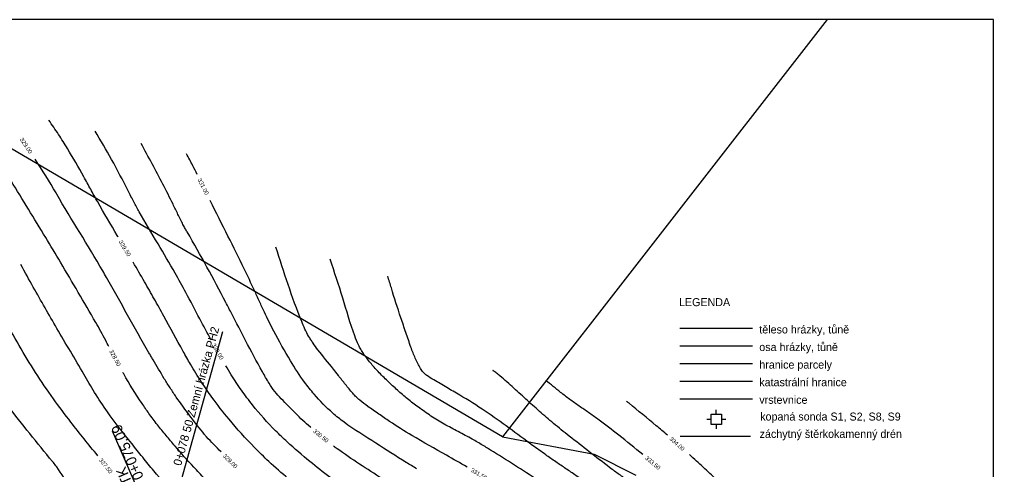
# Model space of a CAD drawing. Extents: x -564037 to -563827, y -1163561 to -1163412.
# Drawn here: x -563942.8 to -563826.5, y -1163466.2 to -1163412.5 of the extents above; entities that cross this region are included whole.
import ezdxf

# ---------------------------------------------------------------- set-up
doc = ezdxf.new("R2010")
doc.units = 0
for name, color, linetype in [('_popis staničení RT1', 7, 'Continuous'), ('_rám RT1', 7, 'Continuous'), ('Hranice parcel', 7, 'Continuous'), ('Obvod PU', 7, 'Continuous'), ('Vrstva 24', 7, 'Continuous'), ('Vrstva 25', 7, 'Continuous'), ('Vrstva 26', 7, 'Continuous')]:
    doc.layers.add(name, color=color, linetype=linetype)

msp = doc.modelspace()

# ---------------------------------------------------------------- linework, layer by layer
at = {"layer": '_popis staničení RT1'}
for points in [[(-563918.58, -1163449.81), (-563924.36, -1163470.65)], [(-563931.75, -1163461.62), (-563927.7, -1163470.89)]]:
    msp.add_lwpolyline(points, dxfattribs=at)
at = {"layer": '_rám RT1'}
for p, q in [((-563826.51, -1163412.49), (-564036.51, -1163412.49)), ((-563826.51, -1163560.99), (-563826.51, -1163412.49)), ((-563863.94, -1163449.37), (-563855.28, -1163449.37)), ((-563863.94, -1163451.47), (-563855.28, -1163451.47)), ((-563863.94, -1163453.57), (-563855.28, -1163453.57)), ((-563863.94, -1163455.68), (-563855.28, -1163455.68)), ((-563863.94, -1163457.78), (-563855.28, -1163457.78)), ((-563859.61, -1163459.62), (-563859.61, -1163459.12)), ((-563860.23, -1163460.27), (-563860.73, -1163460.27)), ((-563858.98, -1163460.24), (-563858.48, -1163460.24)), ((-563859.62, -1163460.87), (-563859.62, -1163461.37)), ((-563863.91, -1163462.26), (-563855.54, -1163462.26))]:
    msp.add_line(p, q, dxfattribs=at)
msp.add_lwpolyline([(-563860.23, -1163459.62), (-563858.98, -1163459.62), (-563858.98, -1163460.87), (-563860.23, -1163460.87)], close=True, dxfattribs=at)
at = {"layer": 'Hranice parcel'}
msp.add_lwpolyline([(-563885.14, -1163462.32), (-563943.67, -1163427.99), (-563964.47, -1163416.08)], dxfattribs=at)
at = {"layer": 'Obvod PU'}
for points in [[(-563846.38, -1163412.49), (-563885.14, -1163462.32)], [(-563885.14, -1163462.32), (-563874.2, -1163464.42), (-563869.21, -1163466.93)]]:
    msp.add_lwpolyline(points, dxfattribs=at)
at = {"layer": 'Vrstva 24'}
for points in [[(-563918.73, -1163464.14), (-563920.47, -1163462.33), (-563920.75, -1163462.02), (-563920.93, -1163461.79), (-563924.08, -1163457.59), (-563924.81, -1163456.5), (-563925.51, -1163455.39), (-563926.86, -1163453.13), (-563927.09, -1163452.73), (-563927.34, -1163452.3), (-563929.89, -1163447.79), (-563932.42, -1163443.31), (-563932.86, -1163442.53), (-563938.36, -1163433.35), (-563938.44, -1163433.21), (-563940.92, -1163429.19)], [(-563921.58, -1163430.99), (-563922.1, -1163429.96), (-563922.86, -1163428.53)], [(-563895.38, -1163466.15), (-563896.62, -1163465.4), (-563900.27, -1163463.09), (-563904.04, -1163460.59), (-563905.39, -1163459.51), (-563907.61, -1163457.24), (-563908.76, -1163455.82), (-563910.43, -1163453.26), (-563912.44, -1163449.7), (-563913.55, -1163447.46), (-563914.15, -1163446.16), (-563914.75, -1163444.86), (-563915.97, -1163442.27), (-563917.91, -1163438.37), (-563920.03, -1163434.12)], [(-563919.38, -1163476.01), (-563920.12, -1163475.14), (-563923.22, -1163471.06), (-563923.7, -1163470.36), (-563924.16, -1163469.69), (-563926.77, -1163466.4), (-563928.09, -1163464.78), (-563929.4, -1163463.14), (-563932.31, -1163459.34), (-563933.83, -1163457.04), (-563935.11, -1163454.85), (-563938.34, -1163449.38), (-563939.75, -1163446.92), (-563941.15, -1163444.46), (-563942.64, -1163441.76)], [(-563881.22, -1163467.31), (-563886.92, -1163463.69), (-563888.12, -1163462.97), (-563888.75, -1163462.61), (-563889.58, -1163462.16), (-563890.42, -1163461.71), (-563891.25, -1163461.27), (-563892.09, -1163460.81), (-563893.67, -1163459.85), (-563894.43, -1163459.32), (-563895.18, -1163458.78), (-563896.46, -1163457.8), (-563897.67, -1163456.77), (-563898.84, -1163455.68), (-563899.98, -1163454.54), (-563900.9, -1163453.5), (-563901.73, -1163452.38), (-563902.04, -1163451.88), (-563902.33, -1163451.36), (-563902.78, -1163450.28), (-563904.21, -1163445.76), (-563905.71, -1163441.12)], [(-563862.95, -1163472.88), (-563865.36, -1163470.94), (-563867.28, -1163469.56), (-563868.39, -1163468.78), (-563869.51, -1163468), (-563870.63, -1163467.22), (-563871.74, -1163466.44), (-563872.34, -1163465.99), (-563877.17, -1163462.24), (-563879.04, -1163460.73), (-563880.71, -1163459.29), (-563882.35, -1163457.82), (-563883.98, -1163456.34), (-563885.65, -1163454.89), (-563886.03, -1163454.58), (-563886.15, -1163454.49), (-563886.22, -1163454.45), (-563886.25, -1163454.42), (-563886.27, -1163454.41)], [(-563865.43, -1163462.14), (-563866.77, -1163461.01), (-563870.02, -1163458.33), (-563870.14, -1163458.23), (-563870.19, -1163458.19), (-563870.34, -1163458.09)], [(-563941.26, -1163493.01), (-563939, -1163490.7), (-563935.17, -1163486.58), (-563933.6, -1163484.77), (-563933.04, -1163483.79), (-563932.45, -1163481.94), (-563932.39, -1163481.58), (-563932.34, -1163479.09), (-563932.36, -1163478.88), (-563932.37, -1163478.7), (-563932.36, -1163477.98), (-563932.29, -1163477.27), (-563932.23, -1163476.55), (-563932.24, -1163475.83), (-563932.27, -1163475.75), (-563932.33, -1163475.65), (-563935.19, -1163471.03), (-563938.35, -1163465.93), (-563938.45, -1163465.79), (-563938.86, -1163465.28), (-563944.23, -1163458.58)], [(-563834.56, -1163494.64), (-563836.37, -1163491.68), (-563837.26, -1163490.4), (-563838.09, -1163489.32), (-563838.93, -1163488.26), (-563840.68, -1163486.18), (-563843.6, -1163482.93), (-563845.38, -1163480.99), (-563847.69, -1163478.52), (-563848.87, -1163477.31), (-563850.08, -1163476.13), (-563853.18, -1163473.26), (-563856.32, -1163470.43), (-563856.74, -1163470.06), (-563856.9, -1163469.93), (-563857.18, -1163469.67), (-563858.78, -1163468.19), (-563860.37, -1163466.7), (-563861.97, -1163465.22), (-563862.81, -1163464.45)]]:
    msp.add_spline(points, degree=3, dxfattribs=at)
at = {"layer": 'Vrstva 25'}
for points in [[(-563919.9, -1163450.79), (-563921.28, -1163448.23), (-563922.95, -1163445.09), (-563924.22, -1163442.79), (-563926.26, -1163439.27), (-563928.5, -1163435.47), (-563929.15, -1163434.28), (-563929.83, -1163432.95), (-563931.81, -1163429.21), (-563933.77, -1163425.82)], [(-563887.06, -1163480.68), (-563889.48, -1163478.12), (-563890.68, -1163477.11), (-563891.26, -1163476.71), (-563892.36, -1163476), (-563898.34, -1163472.15), (-563901.29, -1163470.25), (-563905.74, -1163467.17), (-563908.13, -1163465.28), (-563910.84, -1163462.93), (-563912.22, -1163461.62), (-563914.97, -1163458.53), (-563915.64, -1163457.66), (-563916.29, -1163456.77), (-563917.51, -1163454.93), (-563918.17, -1163453.84)]]:
    msp.add_spline(points, degree=3, dxfattribs=at)
at = {"layer": 'Vrstva 26'}
for points in [[(-563932.12, -1163451.55), (-563932.51, -1163450.83), (-563933.08, -1163449.75), (-563933.69, -1163448.68), (-563937.9, -1163441.49), (-563939.67, -1163438.54), (-563943.81, -1163431.76), (-563944.65, -1163430.42), (-563945.42, -1163429.3), (-563947.84, -1163425.66), (-563950.04, -1163421.85), (-563951.29, -1163419.54), (-563951.84, -1163418.69), (-563952.5, -1163417.84), (-563953.82, -1163416.23)], [(-563931.02, -1163438.49), (-563931.13, -1163438.3), (-563933.46, -1163434.28), (-563933.88, -1163433.53), (-563934.3, -1163432.77), (-563934.71, -1163432.02), (-563935.13, -1163431.27), (-563937.07, -1163427.91), (-563938.14, -1163426.22), (-563939.3, -1163424.52)], [(-563908.01, -1163461.23), (-563908.06, -1163461.19), (-563909.84, -1163459.52), (-563911.55, -1163457.78), (-563912.31, -1163456.93), (-563913, -1163455.94), (-563913.8, -1163454.56), (-563915.81, -1163450.84), (-563917.45, -1163447.66), (-563918.16, -1163446.3), (-563922.78, -1163437.87), (-563923.03, -1163437.44), (-563923.28, -1163436.98), (-563923.88, -1163435.77), (-563924.47, -1163434.56), (-563925.68, -1163432.16), (-563928.28, -1163427.3)], [(-563933.46, -1163464.59), (-563936.66, -1163460.58), (-563938.76, -1163457.78), (-563942.84, -1163451.43), (-563944.76, -1163447.97), (-563948.45, -1163440.73), (-563949, -1163439.65), (-563949.55, -1163438.67), (-563950.17, -1163437.66), (-563950.81, -1163436.67), (-563951.44, -1163435.67), (-563952.06, -1163434.65), (-563954.29, -1163430.74), (-563955.08, -1163429.28)], [(-563889.36, -1163465.94), (-563891.82, -1163464.54), (-563895.95, -1163462.17), (-563898.61, -1163460.5), (-563899.91, -1163459.61), (-563901.2, -1163458.7), (-563902.16, -1163457.97), (-563902.61, -1163457.57), (-563903.02, -1163457.13), (-563903.88, -1163456.08), (-563904.72, -1163455.02), (-563905.32, -1163454.24), (-563907.18, -1163451.93), (-563907.75, -1163451.15), (-563908.02, -1163450.74), (-563908.28, -1163450.32), (-563909.1, -1163448.57), (-563912.19, -1163439.67)], [(-563903.21, -1163473.11), (-563903.34, -1163473.04), (-563904.67, -1163472.17), (-563906.5, -1163470.85), (-563910.71, -1163467.34), (-563913.03, -1163465.28), (-563914.75, -1163463.59), (-563917.78, -1163460.23), (-563919.82, -1163457.6), (-563921.06, -1163455.8), (-563922.39, -1163453.66), (-563923.26, -1163452.13), (-563925.57, -1163447.92), (-563926.72, -1163445.85), (-563927.87, -1163443.82), (-563929.22, -1163441.49)], [(-563871.86, -1163470.11), (-563873.03, -1163469.28), (-563875.16, -1163467.79), (-563876.36, -1163466.96), (-563877.56, -1163466.14), (-563878.77, -1163465.32), (-563879.97, -1163464.48), (-563881.54, -1163463.35), (-563887.19, -1163459.27), (-563890.24, -1163457.35), (-563891.79, -1163456.44), (-563893.34, -1163455.52), (-563894.17, -1163455), (-563894.59, -1163454.63), (-563894.92, -1163454.18), (-563895.24, -1163453.56), (-563895.54, -1163452.93), (-563896.06, -1163451.64), (-563896.67, -1163449.88), (-563897.27, -1163448.11), (-563898.4, -1163444.56), (-563898.83, -1163443.13)], [(-563945.26, -1163485.58), (-563942.43, -1163481.61), (-563942.36, -1163481.51), (-563941.86, -1163480.72), (-563941.1, -1163479.34), (-563940.18, -1163477.03), (-563940.14, -1163476.81), (-563940.11, -1163476.58), (-563939.74, -1163474.25), (-563939.83, -1163473.92), (-563940.07, -1163473.54), (-563942.89, -1163468.84), (-563943.52, -1163467.68), (-563944.1, -1163466.49), (-563944.69, -1163465.31), (-563945.31, -1163464.14), (-563945.97, -1163463.14), (-563948.42, -1163460.21), (-563952.01, -1163455.85), (-563952.99, -1163454.39), (-563953.59, -1163453.33), (-563954.16, -1163452.26), (-563954.74, -1163451.18), (-563955.25, -1163450.27)], [(-563905.62, -1163487.17), (-563905.71, -1163486.43), (-563906.14, -1163484.4), (-563906.33, -1163483.59), (-563906.62, -1163482.77), (-563906.83, -1163482.38), (-563907.08, -1163482.01), (-563907.56, -1163481.45), (-563908.07, -1163480.92), (-563908.73, -1163480.27), (-563912.1, -1163476.61), (-563915.34, -1163473.08), (-563915.91, -1163472.42), (-563916.76, -1163471.47), (-563918.06, -1163470.07), (-563919.38, -1163468.7), (-563920.7, -1163467.33), (-563922, -1163465.94), (-563924.22, -1163463.46), (-563925.29, -1163462.19), (-563926.34, -1163460.89), (-563927.35, -1163459.54), (-563928.17, -1163458.34), (-563930.36, -1163454.82), (-563930.46, -1163454.64)], [(-563868.37, -1163464.45), (-563871.25, -1163462.13), (-563873.73, -1163460.24), (-563874.85, -1163459.44), (-563875.98, -1163458.66), (-563877.1, -1163457.87), (-563878.19, -1163457.03), (-563879.96, -1163455.58)], [(-563873.45, -1163489.45), (-563873.73, -1163488.98), (-563874.78, -1163487.44), (-563876.78, -1163484.89), (-563881.14, -1163480.24), (-563883.66, -1163478.01), (-563887.51, -1163475.07), (-563890.54, -1163473.02), (-563896.23, -1163469.44), (-563897.37, -1163468.71), (-563897.94, -1163468.34), (-563899.48, -1163467.35), (-563904.89, -1163463.75), (-563905.31, -1163463.45)]]:
    msp.add_spline(points, degree=3, dxfattribs=at)

# ---------------------------------------------------------------- texts
at = {"layer": '_popis staničení RT1'}
for s, height, rotation, p in [('0+078 50 Zemní hrázka PH2', 1, 74.4986, (-563923.51, -1163465.86)), ('0+075.09', 1.25, 113.6313, (-563927.94, -1163467.15)), ('TK ', 1.25, 113.6313, (-563929.32, -1163467.75))]:
    msp.add_text(s, height=height, rotation=rotation, dxfattribs=at).set_placement(p)
at = {"layer": '_rám RT1'}
for s, p in [('LEGENDA', (-563864.06, -1163446.73)), ('těleso hrázky, tůně', (-563854.47, -1163449.99)), ('osa hrázky, tůně', (-563854.47, -1163452.09)), ('hranice parcely', (-563854.47, -1163454.19)), ('katastrální hranice', (-563854.47, -1163456.29)), ('vrstevnice', (-563854.47, -1163458.39)), ('kopaná sonda S1, S2, S8, S9', (-563854.36, -1163460.39)), ('záchytný štěrkokamenný drén', (-563854.43, -1163462.46))]:
    msp.add_text(s, height=0.956, rotation=360, dxfattribs=at).set_placement(p)
at = {"layer": 'Vrstva 25'}
for s, rotation, p in [('329.00', 303.5957, (-563942.8, -1163426.82)), ('331.00', 296.3844, (-563921.55, -1163431.62)), ('329.50', 300.895, (-563930.98, -1163439.04)), ('330.00', 299.4755, (-563919.87, -1163451.35)), ('328.50', 298.2595, (-563932.11, -1163452.1)), ('330.50', 320.8421, (-563907.79, -1163461.74)), ('334.00', 318.7306, (-563865.24, -1163462.66)), ('327.50', 308.6467, (-563933.35, -1163465.13)), ('329.00', 314.6992, (-563918.56, -1163464.66)), ('333.50', 320.2433, (-563868.15, -1163464.96)), ('331.50', 329.5681, (-563888.98, -1163466.46))]:
    msp.add_text(s, height=0.5, rotation=rotation, dxfattribs=at).set_placement(p)

doc.saveas('drawing.dxf')
